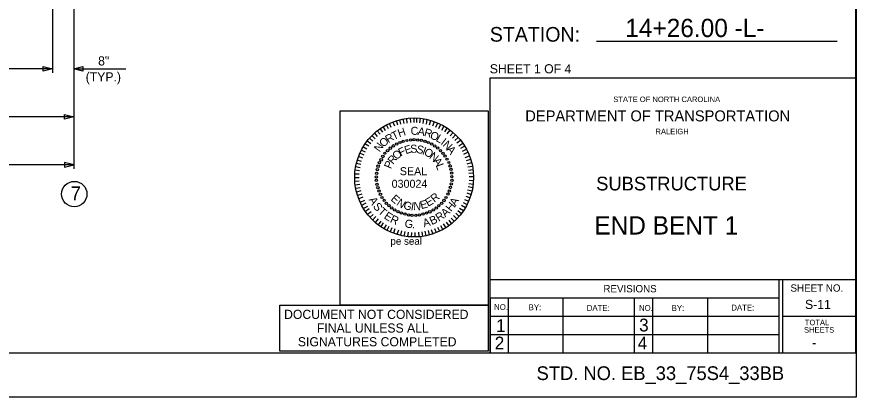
# Model space of a CAD drawing. Extents: x -41 to 191, y -168 to 6.
# Drawn here: x 49.44 to 75.71, y -50.38 to -38.48 of the extents above; entities that cross this region are included whole.
import ezdxf

# ---------------------------------------------------------------- set-up
doc = ezdxf.new("R2010")
doc.units = 0
for name, color, linetype in [('Arrowhead Terminators CELL', 7, 'Continuous'), ('Dimension Lines', 7, 'Continuous'), ('Peseal', 7, 'Continuous'), ('Plan Sheet CELL', 7, 'Continuous'), ('Plot Shape CELL', 7, 'Continuous'), ('Sheet Sticker Exception Certification CELL', 7, 'Continuous'), ('Subtitle Text', 7, 'Continuous'), ('Text', 7, 'Continuous'), ('Title Text', 7, 'Continuous'), ('User Information Notes', 7, 'Continuous'), ('User Information Notes CELL', 7, 'Continuous')]:
    doc.layers.add(name, color=color, linetype=linetype)

msp = doc.modelspace()

# ---------------------------------------------------------------- linework, layer by layer
at = {"layer": 'Arrowhead Terminators CELL'}
for points in [[(50.552, -40.11), (50.266, -40.181), (50.266, -40.038)], [(51.219, -40.11), (51.505, -40.038), (51.505, -40.181)], [(51.219, -41.61), (50.933, -41.681), (50.933, -41.538)], [(51.219, -43.11), (50.933, -43.038), (50.933, -43.181)]]:
    msp.add_lwpolyline(points, close=True, dxfattribs=at)
at = {"layer": 'Dimension Lines'}
for p, q in [((50.552, -35.81), (50.552, -40.235)), ((51.219, -35.86), (51.219, -43.235)), ((50.552, -40.11), (45.886, -40.11)), ((51.219, -40.11), (52.849, -40.11)), ((51.219, -41.61), (45.219, -41.61)), ((51.219, -43.11), (45.219, -43.11))]:
    msp.add_line(p, q, dxfattribs=at)
msp.add_circle((51.238, -44.025), 0.397, dxfattribs=at)
at = {"layer": 'Peseal'}
for p, q in [((61.268, -41.905), (61.214, -41.771)), ((61.366, -41.87), (61.321, -41.726)), ((61.465, -41.843), (61.429, -41.7)), ((61.563, -41.816), (61.536, -41.673)), ((61.661, -41.807), (61.643, -41.664)), ((61.769, -41.789), (61.76, -41.646)), ((61.876, -41.789), (61.876, -41.646)), ((61.957, -41.789), (61.965, -41.646)), ((62.055, -41.798), (62.073, -41.655)), ((62.162, -41.816), (62.18, -41.673)), ((62.261, -41.834), (62.288, -41.691)), ((62.359, -41.861), (62.395, -41.717)), ((62.457, -41.887), (62.511, -41.753)), ((60.892, -42.093), (60.812, -41.977)), ((60.981, -42.039), (60.91, -41.914)), ((61.071, -41.986), (61.008, -41.861)), ((61.16, -41.941), (61.107, -41.816)), ((62.556, -41.932), (62.618, -41.798)), ((62.654, -41.977), (62.717, -41.843)), ((62.744, -42.022), (62.815, -41.896)), ((62.833, -42.084), (62.914, -41.959)), ((62.914, -42.138), (63.003, -42.031)), ((60.588, -42.37), (60.481, -42.281)), ((60.659, -42.299), (60.552, -42.192)), ((60.731, -42.227), (60.642, -42.12)), ((60.812, -42.156), (60.722, -42.048)), ((63.003, -42.209), (63.093, -42.102)), ((63.075, -42.272), (63.173, -42.174)), ((63.146, -42.353), (63.254, -42.254)), ((60.4, -42.621), (60.275, -42.549)), ((60.463, -42.531), (60.337, -42.451)), ((60.516, -42.451), (60.409, -42.37)), ((63.209, -42.424), (63.325, -42.335)), ((63.28, -42.514), (63.397, -42.433)), ((63.334, -42.594), (63.45, -42.523)), ((60.311, -42.809), (60.176, -42.746)), ((60.355, -42.719), (60.221, -42.648)), ((63.388, -42.684), (63.513, -42.621)), ((63.433, -42.782), (63.558, -42.719)), ((63.477, -42.88), (63.611, -42.827)), ((60.203, -43.104), (60.069, -43.068)), ((60.23, -43.006), (60.096, -42.961)), ((60.266, -42.907), (60.132, -42.854)), ((63.513, -42.979), (63.647, -42.934)), ((63.54, -43.077), (63.674, -43.041)), ((60.167, -43.301), (60.033, -43.283)), ((60.185, -43.202), (60.042, -43.176)), ((63.558, -43.176), (63.701, -43.149)), ((63.576, -43.274), (63.719, -43.256)), ((60.159, -43.408), (60.015, -43.399)), ((60.159, -43.515), (60.015, -43.515)), ((63.585, -43.372), (63.728, -43.363)), ((63.594, -43.48), (63.737, -43.48)), ((63.594, -43.587), (63.737, -43.596)), ((60.159, -43.623), (60.015, -43.632)), ((60.176, -43.73), (60.033, -43.748)), ((60.185, -43.829), (60.051, -43.855)), ((63.567, -43.793), (63.71, -43.82)), ((63.585, -43.694), (63.728, -43.712)), ((60.212, -43.927), (60.069, -43.963)), ((60.239, -44.025), (60.105, -44.07)), ((60.275, -44.124), (60.141, -44.177)), ((63.495, -44.088), (63.629, -44.142)), ((63.522, -43.99), (63.665, -44.034)), ((63.549, -43.891), (63.692, -43.927)), ((60.32, -44.222), (60.185, -44.285)), ((60.364, -44.312), (60.23, -44.383)), ((63.361, -44.374), (63.486, -44.446)), ((63.406, -44.285), (63.54, -44.347)), ((63.45, -44.195), (63.585, -44.249)), ((60.418, -44.41), (60.293, -44.482)), ((60.472, -44.491), (60.355, -44.571)), ((60.534, -44.58), (60.418, -44.669)), ((60.597, -44.66), (60.498, -44.75)), ((63.182, -44.625), (63.289, -44.723)), ((63.245, -44.544), (63.361, -44.634)), ((63.298, -44.464), (63.424, -44.544)), ((60.677, -44.732), (60.57, -44.839)), ((60.749, -44.804), (60.659, -44.911)), ((60.829, -44.875), (60.749, -44.983)), ((60.91, -44.929), (60.829, -45.045)), ((62.878, -44.902), (62.958, -45.018)), ((62.958, -44.839), (63.048, -44.956)), ((63.039, -44.777), (63.128, -44.875)), ((63.11, -44.696), (63.218, -44.804)), ((60.999, -44.983), (60.928, -45.108)), ((61.089, -45.036), (61.026, -45.161)), ((61.178, -45.081), (61.125, -45.206)), ((61.277, -45.117), (61.232, -45.251)), ((61.384, -45.152), (61.339, -45.287)), ((61.482, -45.179), (61.447, -45.314)), ((62.216, -45.188), (62.243, -45.331)), ((62.314, -45.17), (62.35, -45.305)), ((62.413, -45.135), (62.457, -45.278)), ((62.511, -45.099), (62.565, -45.233)), ((62.61, -45.063), (62.672, -45.188)), ((62.699, -45.009), (62.771, -45.144)), ((62.788, -44.956), (62.869, -45.081)), ((61.581, -45.197), (61.554, -45.34)), ((61.688, -45.215), (61.67, -45.358)), ((61.796, -45.224), (61.787, -45.367)), ((61.903, -45.224), (61.903, -45.367)), ((62.01, -45.215), (62.019, -45.358)), ((62.118, -45.206), (62.135, -45.349))]:
    msp.add_line(p, q, dxfattribs=at)
for centre, radius in [((61.764, -42.335), 0.0361), ((61.876, -42.326), 0.0358), ((61.988, -42.335), 0.0361), ((61.129, -42.59), 0.0385), ((61.227, -42.518), 0.0385), ((61.33, -42.46), 0.04), ((61.433, -42.411), 0.0341), ((61.536, -42.375), 0.0326), ((61.648, -42.348), 0.0316), ((62.1, -42.344), 0.0369), ((62.216, -42.375), 0.0326), ((62.319, -42.411), 0.0341), ((62.422, -42.464), 0.0361), ((62.52, -42.518), 0.0361), ((62.614, -42.585), 0.0349), ((60.897, -42.849), 0.0385), ((60.959, -42.751), 0.0316), ((61.044, -42.666), 0.038), ((62.703, -42.666), 0.0349), ((62.78, -42.751), 0.0349), ((62.847, -42.836), 0.0361), ((60.789, -43.046), 0.0341), ((60.843, -42.952), 0.0412), ((62.909, -42.934), 0.0361), ((62.963, -43.037), 0.0341), ((60.704, -43.377), 0.0361), ((60.722, -43.265), 0.0369), ((60.749, -43.153), 0.0382), ((63.003, -43.144), 0.0382), ((63.03, -43.256), 0.0369), ((63.048, -43.368), 0.0361), ((60.695, -43.489), 0.0358), ((60.695, -43.6), 0.0361), ((63.057, -43.48), 0.0358), ((63.057, -43.592), 0.0361), ((60.713, -43.717), 0.0361), ((60.74, -43.829), 0.0369), ((63.012, -43.82), 0.0369), ((63.039, -43.708), 0.0361), ((60.776, -43.931), 0.0382), ((60.82, -44.034), 0.04), ((60.87, -44.133), 0.0361), ((62.873, -44.133), 0.0361), ((62.936, -44.025), 0.0361), ((62.976, -43.931), 0.0382), ((60.937, -44.218), 0.0349), ((61.008, -44.312), 0.038), ((61.089, -44.392), 0.038), ((62.65, -44.392), 0.0349), ((62.735, -44.316), 0.0349), ((62.811, -44.227), 0.0385), ((61.174, -44.459), 0.0385), ((61.268, -44.522), 0.0361), ((61.371, -44.576), 0.0341), ((61.478, -44.616), 0.0382), ((61.59, -44.652), 0.0369), ((61.702, -44.678), 0.0361), ((61.813, -44.687), 0.0358), ((61.93, -44.687), 0.0358), ((62.042, -44.678), 0.0361), ((62.153, -44.652), 0.0369), ((62.265, -44.62), 0.0341), ((62.368, -44.58), 0.04), ((62.475, -44.522), 0.0361), ((62.569, -44.464), 0.0349)]:
    msp.add_circle(centre, radius, dxfattribs=at)
at = {"layer": 'Plan Sheet CELL'}
for p, q in [((75.694, -0.902), (75.694, -48.992)), ((75.122, -39.258), (67.589, -39.258)), ((75.694, -40.403), (64.245, -40.403)), ((64.245, -40.403), (64.245, -48.992)), ((64.245, -46.701), (75.694, -46.701)), ((73.291, -46.701), (73.291, -48.992)), ((73.405, -46.701), (73.405, -48.992)), ((64.245, -47.273), (73.295, -47.273)), ((64.252, -47.273), (64.252, -48.992)), ((64.817, -47.273), (64.817, -48.992)), ((66.534, -47.283), (66.534, -49)), ((68.769, -47.273), (68.769, -49.006)), ((69.343, -47.273), (69.343, -48.993)), ((71.06, -47.273), (71.06, -48.993)), ((64.245, -47.846), (73.314, -47.846)), ((73.405, -47.846), (75.674, -47.846)), ((64.245, -48.418), (73.295, -48.418)), ((2.414, -48.992), (75.694, -48.992)), ((75.715, -50.38), (75.715, -50.38))]:
    msp.add_line(p, q, dxfattribs=at)
at = {"layer": 'Plot Shape CELL'}
msp.add_lwpolyline([(0, 0), (75.715, 0), (75.715, -50.38), (0, -50.38)], close=True, dxfattribs=at)
at = {"layer": 'Sheet Sticker Exception Certification CELL'}
msp.add_lwpolyline([(57.671, -47.499), (64.195, -47.499), (64.195, -48.935), (57.671, -48.935)], close=True, dxfattribs=at)
at = {"layer": 'User Information Notes'}
msp.add_line((61.876, -43.507), (61.876, -43.507), dxfattribs=at)
at = {"layer": 'User Information Notes CELL'}
msp.add_line((61.876, -43.507), (61.876, -43.507), dxfattribs=at)
msp.add_lwpolyline([(59.557, -41.417), (64.195, -41.417), (64.195, -47.499), (59.557, -47.499)], close=True, dxfattribs=at)
msp.add_circle((61.876, -43.507), 1.861, dxfattribs=at)

# ---------------------------------------------------------------- texts
at = {"layer": 'Peseal'}
for s, height, rotation, p in [('T', 0.25, 25.943, (61.241, -42.344)), ('H', 0.25, 18.9162, (61.411, -42.254)), ('C', 0.25, 4.8625, (61.778, -42.183)), ('A', 0.25, 350.8088, (61.974, -42.174)), ('R', 0.25, 343.7819, (62.171, -42.201)), ('O', 0.25, 39.9967, (60.91, -42.576)), ('R', 0.25, 32.9699, (61.071, -42.442)), ('O', 0.25, 336.7551, (62.35, -42.272)), ('L', 0.25, 329.7282, (62.538, -42.353)), ('I', 0.25, 322.7014, (62.69, -42.451)), ('N', 0.25, 54.0504, (60.794, -42.728)), ('F', 0.25, 26.4777, (61.456, -42.854)), ('E', 0.25, 18.4448, (61.617, -42.782)), ('S', 0.25, 2.3789, (61.76, -42.737)), ('S', 0.25, 346.313, (61.93, -42.728)), ('I', 0.25, 338.28, (62.109, -42.773)), ('N', 0.25, 315.6745, (62.753, -42.505)), ('A', 0.25, 308.6477, (62.878, -42.639)), ('R', 0.25, 50.5765, (61.214, -43.113)), ('O', 0.25, 42.5436, (61.33, -42.97)), ('O', 0.25, 330.2471, (62.162, -42.782)), ('N', 0.25, 322.2141, (62.332, -42.889)), ('P', 0.25, 66.6424, (61.151, -43.256)), ('A', 0.25, 306.1483, (62.457, -42.997)), ('L', 0.25, 290.0824, (62.547, -43.122)), ('E', 0.25, 318.5179, (61.125, -44.204)), ('E', 0.25, 30.6815, (62.314, -44.428)), ('R', 0.25, 38.6997, (62.511, -44.303)), ('A', 0.254, 300.3993, (60.445, -44.201)), ('S', 0.254, 309.4349, (60.572, -44.417)), ('N', 0.25, 326.5361, (61.304, -44.356)), ('G', 0.25, 342.5725, (61.518, -44.473)), ('I', 0.25, 350.5906, (61.76, -44.526)), ('N', 0.25, 358.6088, (61.849, -44.526)), ('E', 0.25, 14.6452, (62.1, -44.499)), ('H', 0.254, 51.3597, (63.036, -44.594)), ('A', 0.254, 59.6007, (63.18, -44.417)), ('T', 0.254, 318.1096, (60.724, -44.603)), ('E', 0.254, 327.1453, (60.911, -44.771)), ('R', 0.254, 33.5776, (62.649, -44.897)), ('A', 0.254, 42.3241, (62.851, -44.763)), ('R', 0.254, 335.458, (61.104, -44.897)), ('G', 0.254, 353.3858, (61.569, -45.067)), ('A', 0.254, 15.7955, (62.187, -45.066)), ('B', 0.254, 24.8312, (62.428, -44.998)), ('.', 0.254, 2.1323, (61.81, -45.095))]:
    msp.add_text(s, height=height, rotation=rotation, dxfattribs=at).set_placement(p)
for s, p in [('SEAL', (61.429, -43.435)), ('030024', (61.172, -43.829))]:
    msp.add_text(s, height=0.2505, dxfattribs=at).set_placement(p)
at = {"layer": 'Plan Sheet CELL'}
for s, height, p in [('STATION:', 0.458, (64.245, -39.258)), ('SHEET 1 OF 4', 0.28625, (64.245, -40.25)), ('STATE OF NORTH CAROLINA', 0.17174, (68.109, -41.148)), ('DEPARTMENT OF TRANSPORTATION', 0.34349, (65.355, -41.752)), ('RALEIGH', 0.1717, (69.431, -42.154)), ('REVISIONS', 0.229, (67.8, -47.1)), ('SHEET NO.', 0.229, (73.657, -47.079)), ('NO.', 0.1825, (64.381, -47.65)), ('BY:', 0.1825, (65.462, -47.659)), ('DATE:', 0.1825, (67.281, -47.679)), ('NO.', 0.1825, (68.915, -47.679)), ('BY:', 0.1825, (69.938, -47.681)), ('DATE:', 0.1825, (71.805, -47.669)), ('1', 0.401, (64.441, -48.341)), ('3', 0.401, (68.919, -48.323)), ('TOTAL', 0.1717, (74.106, -48.128)), ('SHEETS', 0.1717, (74.08, -48.36)), ('2', 0.401, (64.399, -48.886)), ('4', 0.401, (68.877, -48.886))]:
    msp.add_text(s, height=height, dxfattribs=at).set_placement(p)
at = {"layer": 'Sheet Sticker Exception Certification CELL'}
for s, p in [('DOCUMENT NOT CONSIDERED', (57.806, -47.931)), ('FINAL UNLESS ALL', (58.832, -48.359)), ('SIGNATURES COMPLETED', (58.237, -48.788))]:
    msp.add_text(s, height=0.28561, dxfattribs=at).set_placement(p)
at = {"layer": 'Subtitle Text'}
for s, p in [('SUBSTRUCTURE', (67.575, -43.912)), ('STD. NO. EB_33_75S4_33BB', (65.709, -49.843))]:
    msp.add_text(s, height=0.429, dxfattribs=at).set_placement(p)
at = {"layer": 'Text'}
for s, height, p in [('14+26.00 -L-', 0.572, (68.485, -39.115)), ('8"', 0.286, (51.984, -40.003)), ('(TYP.)', 0.286, (51.595, -40.503)), ('S-11', 0.286, (74.113, -47.621)), ('-', 0.286, (74.331, -48.816))]:
    msp.add_text(s, height=height, dxfattribs=at).set_placement(p)
at = {"layer": 'Title Text'}
for s, height, p in [('7', 0.429, (51.125, -44.217)), ('END BENT 1', 0.572, (67.516, -45.291))]:
    msp.add_text(s, height=height, dxfattribs=at).set_placement(p)
at = {"layer": 'User Information Notes CELL'}
msp.add_text('pe seal', height=0.229, dxfattribs=at).set_placement((61.134, -45.612))

doc.saveas('drawing.dxf')
